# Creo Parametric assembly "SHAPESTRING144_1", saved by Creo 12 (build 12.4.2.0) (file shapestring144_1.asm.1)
Units: Custom; MM, KILOGRAM, SECS

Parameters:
  PTC_WM_ITERATION = "0"
  PTC_WM_VERSION = "-.0"
  PTC_WM_LIFECYCLE_STATE = "In Work"
  PTC_WM_LIFECYCLE = "MO_CADDocument"
  PTC_WM_CREATED_BY = "Maximilian Roepper (Z0017RMS: MO)"
  PTC_WM_CREATED_ON = "18-Sep-26 11:36:42 AM"
  PTC_WM_MODIFIED_BY = "Maximilian Roepper (Z0017RMS: MO)"
  PTC_WM_MODIFIED_ON = "18-Sep-26 11:36:46 AM"
  PDMLINKNUMBER = "PDM000071455328"
  PTC_WM_NUMBER = "PDM000071455328"

Other parameters: WEIGHT, WEIGHT_FACTOR, WEIGHT_ADD, MC_ERRORS, SUPPLIER

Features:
  1. coordinate system
  2. imported feature
  3. component "SHAPESTRING074_1"
  4. component "SHAPESTRING142_1"
  5. component "SHAPESTRING143_1"

Other named items: DRW_VIEW_ORG, ROUGH-GROB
